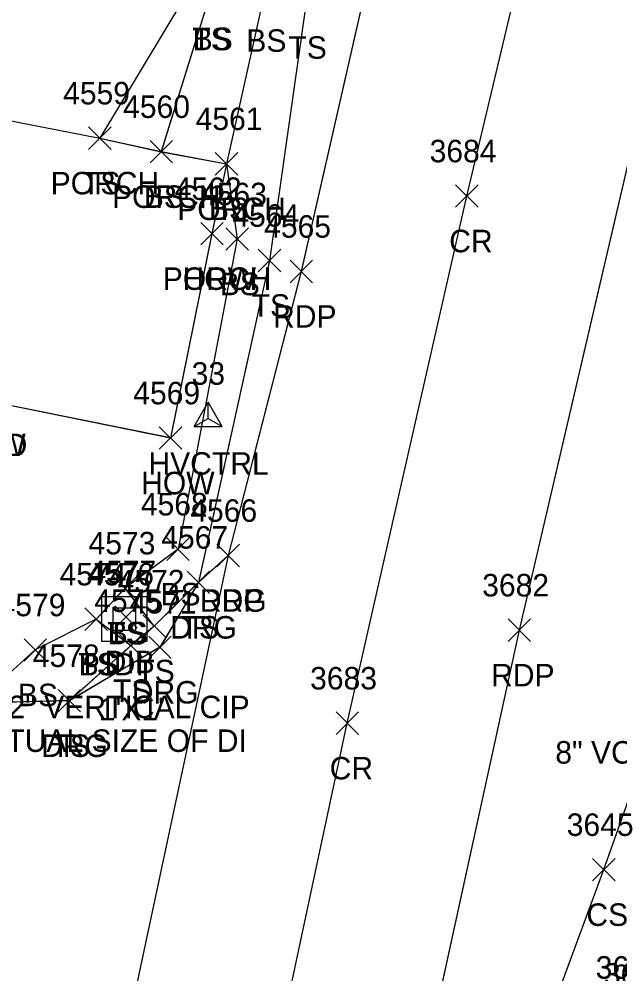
# Model space of a CAD drawing. Extents: x 1554668 to 1563881, y 831386 to 834374.
# Drawn here: x 1562427.9 to 1562481.4, y 833776.4 to 833861.3 of the extents above; entities that cross this region are included whole.
import ezdxf

# ---------------------------------------------------------------- set-up
doc = ezdxf.new("R2010")
doc.units = 0
for name, color, linetype in [('C_A', 7, 'Continuous'), ('C_I', 7, 'Continuous'), ('CPSM', 7, 'Continuous'), ('D_A', 7, 'Continuous'), ('D_C', 7, 'Continuous'), ('D_I', 7, 'Continuous'), ('D_TIC', 7, 'Continuous'), ('DS', 7, 'Continuous'), ('L_A', 7, 'Continuous'), ('L_I', 7, 'Continuous'), ('L_TIC', 7, 'Continuous'), ('LBC', 7, 'Continuous'), ('LBF', 7, 'Continuous'), ('LELB', 7, 'Continuous'), ('P_A', 7, 'Continuous'), ('P_I', 7, 'Continuous'), ('P_TIC', 7, 'Continuous'), ('PET', 7, 'Continuous'), ('PRC', 7, 'Continuous'), ('R_A', 7, 'Continuous'), ('R_I', 7, 'Continuous'), ('R_TIC', 7, 'Continuous'), ('RDG', 7, 'Continuous')]:
    doc.layers.add(name, color=color, linetype=linetype)

msp = doc.modelspace()

# ---------------------------------------------------------------- linework, layer by layer
at = {"layer": 'CPSM'}
for p, q in [((1562443.481, 833825.025), (1562444.731, 833827.19)), ((1562445.981, 833825.025), (1562444.731, 833827.19)), ((1562444.732, 833825.746), (1562444.731, 833827.19)), ((1562443.481, 833825.025), (1562444.732, 833825.746)), ((1562444.732, 833825.746), (1562444.732, 833825.746)), ((1562444.732, 833825.746), (1562445.981, 833825.025)), ((1562443.481, 833825.025), (1562445.981, 833825.025))]:
    msp.add_line(p, q, dxfattribs=at)
at = {"layer": 'D_TIC'}
for points in [[(1562436.431, 833807.096), (1562438.431, 833809.096)], [(1562438.431, 833807.096), (1562436.431, 833809.096)]]:
    msp.add_lwpolyline(points, dxfattribs=at)
at = {"layer": 'DS'}
for p, q in [((1562435.276, 833809.905), (1562439.276, 833809.905)), ((1562435.276, 833805.905), (1562435.276, 833809.905)), ((1562439.276, 833809.905), (1562439.276, 833805.905)), ((1562436.276, 833806.905), (1562436.276, 833808.905)), ((1562436.276, 833808.905), (1562438.276, 833808.905)), ((1562438.276, 833808.905), (1562438.276, 833806.905)), ((1562437.281, 833807.906), (1562437.281, 833807.906)), ((1562437.281, 833807.906), (1562437.281, 833807.906)), ((1562438.276, 833806.905), (1562436.276, 833806.905)), ((1562439.276, 833805.905), (1562435.276, 833805.905))]:
    msp.add_line(p, q, dxfattribs=at)
at = {"layer": 'L_TIC'}
for points in [[(1562434.102, 833849.67), (1562436.102, 833851.67)], [(1562436.102, 833849.67), (1562434.102, 833851.67)], [(1562434.102, 833849.67), (1562436.102, 833851.67)], [(1562436.102, 833849.67), (1562434.102, 833851.67)], [(1562439.566, 833848.466), (1562441.566, 833850.466)], [(1562441.566, 833848.466), (1562439.566, 833850.466)], [(1562439.566, 833848.466), (1562441.566, 833850.466)], [(1562441.566, 833848.466), (1562439.566, 833850.466)], [(1562445.365, 833847.39), (1562447.365, 833849.39)], [(1562447.365, 833847.39), (1562445.365, 833849.39)], [(1562445.365, 833847.39), (1562447.365, 833849.39)], [(1562447.365, 833847.39), (1562445.365, 833849.39)], [(1562444.076, 833841.176), (1562446.076, 833843.176)], [(1562446.076, 833841.176), (1562444.076, 833843.176)], [(1562444.076, 833841.176), (1562446.076, 833843.176)], [(1562446.076, 833841.176), (1562444.076, 833843.176)], [(1562446.325, 833840.702), (1562448.325, 833842.702)], [(1562448.325, 833840.702), (1562446.325, 833842.702)], [(1562449.199, 833838.787), (1562451.199, 833840.787)], [(1562451.199, 833838.787), (1562449.199, 833840.787)], [(1562440.389, 833823.003), (1562442.389, 833825.003)], [(1562442.389, 833823.003), (1562440.389, 833825.003)], [(1562441.057, 833813.122), (1562443.057, 833815.122)], [(1562443.057, 833813.122), (1562441.057, 833815.122)], [(1562442.872, 833810.172), (1562444.872, 833812.172)], [(1562444.872, 833810.172), (1562442.872, 833812.172)], [(1562436.353, 833809.658), (1562438.353, 833811.658)], [(1562438.353, 833809.658), (1562436.353, 833811.658)], [(1562436.353, 833809.658), (1562438.353, 833811.658)], [(1562438.353, 833809.658), (1562436.353, 833811.658)], [(1562433.776, 833806.899), (1562435.776, 833808.899)], [(1562435.776, 833806.899), (1562433.776, 833808.899)], [(1562433.776, 833806.899), (1562435.776, 833808.899)], [(1562435.776, 833806.899), (1562433.776, 833808.899)], [(1562438.94, 833806.285), (1562440.94, 833808.285)], [(1562440.94, 833806.285), (1562438.94, 833808.285)], [(1562438.94, 833806.285), (1562440.94, 833808.285)], [(1562440.94, 833806.285), (1562438.94, 833808.285)], [(1562428.359, 833804.16), (1562430.359, 833806.16)], [(1562430.359, 833804.16), (1562428.359, 833806.16)], [(1562436.862, 833804.544), (1562438.862, 833806.544)], [(1562438.862, 833804.544), (1562436.862, 833806.544)], [(1562436.862, 833804.544), (1562438.862, 833806.544)], [(1562438.862, 833804.544), (1562436.862, 833806.544)], [(1562431.393, 833799.647), (1562433.393, 833801.647)], [(1562433.393, 833799.647), (1562431.393, 833801.647)], [(1562478.951, 833784.626), (1562480.951, 833786.626)], [(1562480.951, 833784.626), (1562478.951, 833786.626)]]:
    msp.add_lwpolyline(points, dxfattribs=at)
at = {"layer": 'LBC'}
for points in [[(1562445.075, 833842.183), (1562441.39, 833824.008), (1562424.584, 833827.399), (1562417.372, 833829.227), (1562419.41, 833839.49), (1562412.483, 833840.561)], [(1562445.075, 833842.183), (1562441.39, 833824.008), (1562424.584, 833827.399), (1562417.372, 833829.227), (1562419.41, 833839.49), (1562412.483, 833840.561)], [(1562445.075, 833842.183), (1562441.39, 833824.008), (1562424.584, 833827.399), (1562417.372, 833829.227), (1562419.41, 833839.49), (1562412.483, 833840.561)], [(1562445.076, 833842.176), (1562441.389, 833824.003), (1562424.584, 833827.394), (1562417.373, 833829.217), (1562419.412, 833839.485), (1562412.484, 833840.549)]]:
    msp.add_lwpolyline(points, dxfattribs=at)
at = {"layer": 'LBF'}
for points in [[(1562422.129, 833851.258), (1562422.749, 833853.075), (1562435.102, 833850.67), (1562440.566, 833849.466), (1562446.365, 833848.39), (1562445.076, 833842.176)], [(1562422.132, 833851.267), (1562422.749, 833853.081), (1562435.102, 833850.678), (1562440.566, 833849.476), (1562446.364, 833848.399), (1562445.075, 833842.183)], [(1562422.132, 833851.267), (1562422.749, 833853.081), (1562435.102, 833850.678), (1562440.566, 833849.476), (1562446.364, 833848.399), (1562445.075, 833842.183)], [(1562422.132, 833851.267), (1562422.749, 833853.081), (1562435.102, 833850.678), (1562440.566, 833849.476), (1562446.364, 833848.399), (1562445.075, 833842.183)]]:
    msp.add_lwpolyline(points, dxfattribs=at)
at = {"layer": 'LELB'}
for points in [[(1562476.834, 833955.648), (1562468.679, 833926.894), (1562468.902, 833924.609), (1562461.224, 833893.664), (1562455.205, 833877.118), (1562454.79, 833874.975), (1562449.701, 833863.357), (1562446.364, 833848.399), (1562447.324, 833841.707), (1562442.057, 833814.133), (1562437.353, 833810.667)], [(1562476.834, 833955.648), (1562468.679, 833926.894), (1562468.902, 833924.609), (1562461.224, 833893.664), (1562455.205, 833877.118), (1562454.79, 833874.975), (1562449.701, 833863.357), (1562446.364, 833848.399), (1562447.324, 833841.707), (1562442.057, 833814.133), (1562437.353, 833810.667)], [(1562476.834, 833955.648), (1562468.679, 833926.894), (1562468.902, 833924.609), (1562461.224, 833893.664), (1562455.205, 833877.118), (1562454.79, 833874.975), (1562449.701, 833863.357), (1562446.364, 833848.399), (1562447.324, 833841.707), (1562442.057, 833814.133), (1562437.353, 833810.667)], [(1562476.835, 833955.638), (1562468.678, 833926.886), (1562468.901, 833924.601), (1562461.216, 833893.654), (1562455.204, 833877.112), (1562454.789, 833874.968), (1562449.695, 833863.347), (1562446.365, 833848.39), (1562447.325, 833841.702), (1562442.057, 833814.122), (1562437.353, 833810.658)], [(1562466.529, 833927.967), (1562468.679, 833926.894), (1562471.345, 833925.231), (1562463.359, 833893.198), (1562459.518, 833878.813), (1562457.062, 833872.471), (1562453.473, 833862.736), (1562450.2, 833839.796), (1562443.872, 833811.177), (1562439.94, 833807.289), (1562437.862, 833805.547), (1562432.393, 833800.653)], [(1562466.529, 833927.967), (1562468.679, 833926.894), (1562471.345, 833925.231), (1562463.359, 833893.198), (1562459.518, 833878.813), (1562457.062, 833872.471), (1562453.473, 833862.736), (1562450.2, 833839.796), (1562443.872, 833811.177), (1562439.94, 833807.289), (1562437.862, 833805.547), (1562432.393, 833800.653)], [(1562466.529, 833927.967), (1562468.679, 833926.894), (1562471.345, 833925.231), (1562463.359, 833893.198), (1562459.518, 833878.813), (1562457.062, 833872.471), (1562453.473, 833862.736), (1562450.2, 833839.796), (1562443.872, 833811.177), (1562439.94, 833807.289), (1562437.862, 833805.547), (1562432.393, 833800.653)], [(1562466.528, 833927.959), (1562468.678, 833926.886), (1562471.341, 833925.223), (1562463.35, 833893.188), (1562459.51, 833878.803), (1562457.062, 833872.466), (1562453.47, 833862.729), (1562450.199, 833839.787), (1562443.872, 833811.172), (1562439.94, 833807.285), (1562437.862, 833805.544), (1562432.393, 833800.647)], [(1562468.902, 833924.609), (1562467.61, 833924.93), (1562459.794, 833894.194), (1562453.32, 833877.396), (1562452.695, 833874.807), (1562444.925, 833863.497), (1562440.566, 833849.476)], [(1562468.902, 833924.609), (1562467.61, 833924.93), (1562459.794, 833894.194), (1562453.32, 833877.396), (1562452.695, 833874.807), (1562444.925, 833863.497), (1562440.566, 833849.476)], [(1562468.902, 833924.609), (1562467.61, 833924.93), (1562459.794, 833894.194), (1562453.32, 833877.396), (1562452.695, 833874.807), (1562444.925, 833863.497), (1562440.566, 833849.476)], [(1562468.901, 833924.601), (1562467.612, 833924.922), (1562459.786, 833894.185), (1562453.32, 833877.39), (1562452.694, 833874.801), (1562444.919, 833863.488), (1562440.566, 833849.466)], [(1562470.712, 833752.478), (1562474.337, 833770.456), (1562479.951, 833785.626), (1562485.543, 833801.396), (1562491.302, 833804.223), (1562493.844, 833813.304), (1562489.93, 833819.122), (1562484.169, 833819.958), (1562491.716, 833857.447), (1562503.171, 833893.196)], [(1562470.713, 833752.487), (1562474.337, 833770.46), (1562479.948, 833785.634), (1562485.546, 833801.399), (1562491.303, 833804.228), (1562493.845, 833813.309), (1562489.932, 833819.127), (1562484.169, 833819.963), (1562491.72, 833857.455), (1562503.176, 833893.205)], [(1562470.713, 833752.487), (1562474.337, 833770.46), (1562479.948, 833785.634), (1562485.546, 833801.399), (1562491.303, 833804.228), (1562493.845, 833813.309), (1562489.932, 833819.127), (1562484.169, 833819.963), (1562491.72, 833857.455), (1562503.176, 833893.205)], [(1562470.713, 833752.487), (1562474.337, 833770.46), (1562479.948, 833785.634), (1562485.546, 833801.399), (1562491.303, 833804.228), (1562493.845, 833813.309), (1562489.932, 833819.127), (1562484.169, 833819.963), (1562491.72, 833857.455), (1562503.176, 833893.205)], [(1562447.141, 833880.224), (1562444.644, 833873.522), (1562444.558, 833866.42), (1562435.102, 833850.678)], [(1562447.141, 833880.224), (1562444.644, 833873.522), (1562444.558, 833866.42), (1562435.102, 833850.678)], [(1562447.141, 833880.224), (1562444.644, 833873.522), (1562444.558, 833866.42), (1562435.102, 833850.678)], [(1562447.145, 833880.221), (1562444.645, 833873.518), (1562444.558, 833866.41), (1562435.102, 833850.67)], [(1562439.94, 833807.289), (1562437.353, 833810.667), (1562434.776, 833807.902), (1562437.862, 833805.547)], [(1562439.94, 833807.289), (1562437.353, 833810.667), (1562434.776, 833807.902), (1562437.862, 833805.547)], [(1562439.94, 833807.289), (1562437.353, 833810.667), (1562434.776, 833807.902), (1562437.862, 833805.547)], [(1562439.94, 833807.285), (1562437.353, 833810.658), (1562434.776, 833807.899), (1562437.862, 833805.544)], [(1562434.776, 833807.902), (1562429.358, 833805.169), (1562424.083, 833800.435)], [(1562434.776, 833807.902), (1562429.358, 833805.169), (1562424.083, 833800.435)], [(1562434.776, 833807.902), (1562429.358, 833805.169), (1562424.083, 833800.435)], [(1562434.776, 833807.899), (1562429.359, 833805.16), (1562424.084, 833800.427)]]:
    msp.add_lwpolyline(points, dxfattribs=at)
at = {"layer": 'P_TIC'}
for points in [[(1562466.753, 833844.523), (1562468.753, 833846.523)], [(1562468.753, 833844.523), (1562466.753, 833846.523)], [(1562452.027, 833837.818), (1562454.027, 833839.818)], [(1562454.027, 833837.818), (1562452.027, 833839.818)], [(1562445.513, 833812.556), (1562447.513, 833814.556)], [(1562447.513, 833812.556), (1562445.513, 833814.556)], [(1562471.429, 833805.92), (1562473.429, 833807.92)], [(1562473.429, 833805.92), (1562471.429, 833807.92)], [(1562456.117, 833797.648), (1562458.117, 833799.648)], [(1562458.117, 833797.648), (1562456.117, 833799.648)]]:
    msp.add_lwpolyline(points, dxfattribs=at)
at = {"layer": 'PET'}
for points in [[(1562390.311, 833375.989), (1562393.977, 833397.67), (1562399.624, 833430.723), (1562404.076, 833456.64), (1562408.479, 833482.044), (1562418.419, 833535.55), (1562424.853, 833574.142), (1562431.347, 833605.093), (1562438.205, 833641.603), (1562449.823, 833698.96), (1562455.982, 833728.945), (1562464.252, 833769.476), (1562472.427, 833806.927), (1562484.773, 833859.846), (1562495.065, 833901.936), (1562505.742, 833945.836), (1562515.589, 833982.411), (1562522.272, 834008.538), (1562529.881, 834035.713), (1562547.387, 834091.493), (1562561.695, 834132.946), (1562566.268, 834145.816)], [(1562390.311, 833375.989), (1562393.977, 833397.67), (1562399.624, 833430.723), (1562404.076, 833456.64), (1562408.479, 833482.044), (1562418.419, 833535.55), (1562424.853, 833574.142), (1562431.347, 833605.093), (1562438.205, 833641.603), (1562449.823, 833698.96), (1562455.982, 833728.945), (1562464.252, 833769.476), (1562472.427, 833806.927), (1562484.773, 833859.846), (1562495.065, 833901.936), (1562505.742, 833945.836), (1562515.589, 833982.411), (1562522.272, 834008.538), (1562529.881, 834035.713), (1562547.387, 834091.493), (1562561.695, 834132.946), (1562566.268, 834145.816)], [(1562390.311, 833375.989), (1562393.977, 833397.67), (1562399.624, 833430.723), (1562404.076, 833456.64), (1562408.479, 833482.044), (1562418.419, 833535.55), (1562424.853, 833574.142), (1562431.347, 833605.093), (1562438.205, 833641.603), (1562449.823, 833698.96), (1562455.982, 833728.945), (1562464.252, 833769.476), (1562472.427, 833806.927), (1562484.773, 833859.846), (1562495.065, 833901.936), (1562505.742, 833945.836), (1562515.589, 833982.411), (1562522.272, 834008.538), (1562529.881, 834035.713), (1562547.387, 834091.493), (1562561.695, 834132.946), (1562566.268, 834145.816)], [(1562390.312, 833375.983), (1562393.977, 833397.668), (1562399.627, 833430.715), (1562404.077, 833456.635), (1562408.483, 833482.042), (1562418.422, 833535.549), (1562424.854, 833574.14), (1562431.348, 833605.09), (1562438.2, 833641.597), (1562449.823, 833698.953), (1562455.981, 833728.934), (1562464.252, 833769.469), (1562472.429, 833806.92), (1562484.77, 833859.84), (1562495.065, 833901.93), (1562505.741, 833945.826), (1562515.584, 833982.407), (1562522.267, 834008.535), (1562529.877, 834035.701), (1562547.383, 834091.48), (1562561.691, 834132.936), (1562566.264, 834145.807)], [(1562435.459, 834067.179), (1562467.01, 834059.144), (1562485.949, 834051.808), (1562489.315, 834049.467), (1562496.216, 834039.663), (1562499.641, 834027.091), (1562496.942, 834013.671), (1562484.997, 833969.829), (1562474.119, 833928.894), (1562465.329, 833892.835), (1562453.027, 833838.818), (1562446.513, 833813.556), (1562435.697, 833762.843)], [(1562435.465, 834067.183), (1562467.015, 834059.149), (1562485.955, 834051.812), (1562489.324, 834049.47), (1562496.226, 834039.666), (1562499.647, 834027.095), (1562496.946, 834013.679), (1562485.004, 833969.835), (1562474.119, 833928.902), (1562465.328, 833892.841), (1562453.028, 833838.829), (1562446.514, 833813.563), (1562435.7, 833762.854)], [(1562435.465, 834067.183), (1562467.015, 834059.149), (1562485.955, 834051.812), (1562489.324, 834049.47), (1562496.226, 834039.666), (1562499.647, 834027.095), (1562496.946, 834013.679), (1562485.004, 833969.835), (1562474.119, 833928.902), (1562465.328, 833892.841), (1562453.028, 833838.829), (1562446.514, 833813.563), (1562435.7, 833762.854)], [(1562435.465, 834067.183), (1562467.015, 834059.149), (1562485.955, 834051.812), (1562489.324, 834049.47), (1562496.226, 834039.666), (1562499.647, 834027.095), (1562496.946, 834013.679), (1562485.004, 833969.835), (1562474.119, 833928.902), (1562465.328, 833892.841), (1562453.028, 833838.829), (1562446.514, 833813.563), (1562435.7, 833762.854)]]:
    msp.add_lwpolyline(points, dxfattribs=at)
at = {"layer": 'PRC'}
for points in [[(1562374.328, 833358.788), (1562379.819, 833391.645), (1562386.805, 833432.043), (1562394.132, 833473.552), (1562401.52, 833515.146), (1562408.626, 833554.57), (1562418.317, 833607.158), (1562425.122, 833644.153), (1562437.129, 833703.517), (1562446.816, 833750.468), (1562457.117, 833798.654), (1562467.75, 833845.524), (1562476.843, 833883.646), (1562492.325, 833945.243), (1562502.519, 833985.558), (1562516.732, 834038.229), (1562535.447, 834096.625), (1562549.682, 834139.255), (1562553.417, 834150.261)], [(1562374.328, 833358.788), (1562379.819, 833391.645), (1562386.805, 833432.043), (1562394.132, 833473.552), (1562401.52, 833515.146), (1562408.626, 833554.57), (1562418.317, 833607.158), (1562425.122, 833644.153), (1562437.129, 833703.517), (1562446.816, 833750.468), (1562457.117, 833798.654), (1562467.75, 833845.524), (1562476.843, 833883.646), (1562492.325, 833945.243), (1562502.519, 833985.558), (1562516.732, 834038.229), (1562535.447, 834096.625), (1562549.682, 834139.255), (1562553.417, 834150.261)], [(1562374.328, 833358.788), (1562379.819, 833391.645), (1562386.805, 833432.043), (1562394.132, 833473.552), (1562401.52, 833515.146), (1562408.626, 833554.57), (1562418.317, 833607.158), (1562425.122, 833644.153), (1562437.129, 833703.517), (1562446.816, 833750.468), (1562457.117, 833798.654), (1562467.75, 833845.524), (1562476.843, 833883.646), (1562492.325, 833945.243), (1562502.519, 833985.558), (1562516.732, 834038.229), (1562535.447, 834096.625), (1562549.682, 834139.255), (1562553.417, 834150.261)], [(1562374.328, 833358.78), (1562379.82, 833391.635), (1562386.804, 833432.041), (1562394.133, 833473.548), (1562401.522, 833515.144), (1562408.625, 833554.563), (1562418.32, 833607.155), (1562425.125, 833644.147), (1562437.128, 833703.511), (1562446.815, 833750.458), (1562457.117, 833798.648), (1562467.753, 833845.523), (1562476.843, 833883.643), (1562492.321, 833945.235), (1562502.515, 833985.553), (1562516.728, 834038.221), (1562535.444, 834096.612), (1562549.678, 834139.252), (1562553.413, 834150.251)]]:
    msp.add_lwpolyline(points, dxfattribs=at)
at = {"layer": 'R_TIC'}
for points in [[(1562445.513, 833812.556), (1562447.513, 833814.556)], [(1562447.513, 833812.556), (1562445.513, 833814.556)], [(1562442.872, 833810.172), (1562444.872, 833812.172)], [(1562444.872, 833810.172), (1562442.872, 833812.172)], [(1562439.453, 833804.4), (1562441.453, 833806.4)], [(1562441.453, 833804.4), (1562439.453, 833806.4)], [(1562431.393, 833799.647), (1562433.393, 833801.647)], [(1562433.393, 833799.647), (1562431.393, 833801.647)]]:
    msp.add_lwpolyline(points, dxfattribs=at)
at = {"layer": 'RDG'}
for points in [[(1562446.514, 833813.563), (1562443.872, 833811.177), (1562440.454, 833805.407), (1562432.393, 833800.653), (1562424.083, 833800.435), (1562417.273, 833767.263), (1562421.889, 833758.153), (1562425.326, 833750.474), (1562429.669, 833734.264)], [(1562446.514, 833813.563), (1562443.872, 833811.177), (1562440.454, 833805.407), (1562432.393, 833800.653), (1562424.083, 833800.435), (1562417.273, 833767.263), (1562421.889, 833758.153), (1562425.326, 833750.474), (1562429.669, 833734.264)], [(1562446.514, 833813.563), (1562443.872, 833811.177), (1562440.454, 833805.407), (1562432.393, 833800.653), (1562424.083, 833800.435), (1562417.273, 833767.263), (1562421.889, 833758.153), (1562425.326, 833750.474), (1562429.669, 833734.264)], [(1562446.513, 833813.556), (1562443.872, 833811.172), (1562440.453, 833805.4), (1562432.393, 833800.647), (1562424.084, 833800.427), (1562417.274, 833767.254), (1562421.893, 833758.146), (1562425.324, 833750.465), (1562429.671, 833734.255)]]:
    msp.add_lwpolyline(points, dxfattribs=at)

# ---------------------------------------------------------------- texts
at = {"layer": 'C_A'}
msp.add_text('HVCTRL', height=2, dxfattribs=at).set_placement((1562439.424, 833820.746))
at = {"layer": 'C_I'}
msp.add_text('33', height=2, dxfattribs=at).set_placement((1562443.267, 833828.746))
at = {"layer": 'D_A'}
for s, p in [('DIB', (1562435.533, 833803.096)), ('DI', (1562436.336, 833802.906))]:
    msp.add_text(s, height=2, dxfattribs=at).set_placement(p)
at = {"layer": 'D_C'}
for s, p in [('12" VERTICAL CIP', (1562425.486, 833799.096)), ("1'X1'", (1562435.013, 833798.906)), ('ACTUAL SIZE OF DI', (1562423.068, 833796.096)), ('8" VCP FLOWING EAST', (1562475.625, 833795.057))]:
    msp.add_text(s, height=2, dxfattribs=at).set_placement(p)
at = {"layer": 'D_I'}
for s, p in [('4577', (1562434.171, 833811.096)), ('4576', (1562433.966, 833810.906))]:
    msp.add_text(s, height=2, dxfattribs=at).set_placement(p)
at = {"layer": 'L_A'}
for s, p in [('TS', (1562443.329, 833858.488)), ('BS', (1562443.36, 833858.488)), ('BS', (1562448.136, 833858.347)), ('TS', (1562451.88, 833857.729)), ('PORCH', (1562430.725, 833845.67)), ('TS', (1562433.512, 833845.67)), ('PORCH', (1562436.188, 833844.466)), ('BS', (1562439.007, 833844.466)), ('PORCH', (1562441.987, 833843.39)), ('BS', (1562444.806, 833843.39)), ('PORCH', (1562440.698, 833837.176)), ('HOW', (1562442.462, 833837.176)), ('BS', (1562445.766, 833836.702)), ('TS', (1562448.609, 833834.787)), ('SHED', (1562421.222, 833822.394)), ('HOW', (1562421.97, 833822.394)), ('HOW', (1562438.775, 833819.003)), ('BS', (1562440.498, 833809.122)), ('TS', (1562442.281, 833806.172)), ('TS', (1562435.762, 833805.658)), ('BS', (1562435.794, 833805.658)), ('TS', (1562433.185, 833802.899)), ('BS', (1562433.216, 833802.899)), ('TS', (1562438.349, 833802.285)), ('TS', (1562438.349, 833802.285)), ('BS', (1562427.8, 833800.16)), ('TS', (1562436.271, 833800.544)), ('TS', (1562436.271, 833800.544)), ('TS', (1562430.802, 833795.647)), ('CS', (1562478.392, 833780.626))]:
    msp.add_text(s, height=2, dxfattribs=at).set_placement(p)
at = {"layer": 'L_I'}
for s, p in [('4559', (1562431.835, 833853.67)), ('4559', (1562431.835, 833853.67)), ('4560', (1562437.172, 833852.466)), ('4560', (1562437.172, 833852.466)), ('4561', (1562443.625, 833851.39)), ('4561', (1562443.625, 833851.39)), ('4562', (1562441.769, 833845.176)), ('4562', (1562441.769, 833845.176)), ('4563', (1562444.018, 833844.702)), ('4564', (1562446.892, 833842.787)), ('4569', (1562438.074, 833827.003)), ('4568', (1562438.75, 833817.122)), ('4573', (1562434.093, 833813.658)), ('4573', (1562434.093, 833813.658)), ('4567', (1562440.565, 833814.172)), ('4574', (1562431.516, 833810.899)), ('4574', (1562431.516, 833810.899)), ('4572', (1562436.68, 833810.285)), ('4572', (1562436.68, 833810.285)), ('4575', (1562434.602, 833808.544)), ('4575', (1562434.602, 833808.544)), ('4579', (1562426.091, 833808.16)), ('4578', (1562429.133, 833803.647)), ('3645', (1562476.644, 833788.626)), ('3642', (1562479.218, 833775.932)), ('3641', (1562479.949, 833775.314))]:
    msp.add_text(s, height=2, dxfattribs=at).set_placement(p)
at = {"layer": 'P_A'}
for s, p in [('CR', (1562466.186, 833840.523)), ('RDP', (1562450.515, 833833.818)), ('RDP', (1562444.001, 833808.556)), ('RDP', (1562469.917, 833801.92)), ('CR', (1562455.55, 833793.648))]:
    msp.add_text(s, height=2, dxfattribs=at).set_placement(p)
at = {"layer": 'P_I'}
for s, p in [('3684', (1562464.446, 833848.523)), ('4565', (1562449.72, 833841.818)), ('4566', (1562443.151, 833816.556)), ('3682', (1562469.122, 833809.92)), ('3683', (1562453.81, 833801.648))]:
    msp.add_text(s, height=2, dxfattribs=at).set_placement(p)
at = {"layer": 'R_A'}
for p in [(1562444.001, 833808.556), (1562441.36, 833806.172), (1562437.942, 833800.4), (1562429.881, 833795.647)]:
    msp.add_text('DRG', height=2, dxfattribs=at).set_placement(p)
at = {"layer": 'R_I'}
for s, p in [('4566', (1562443.151, 833816.556)), ('4567', (1562440.565, 833814.172)), ('4571', (1562437.76, 833808.4)), ('4578', (1562429.133, 833803.647)), ('3642', (1562479.218, 833775.932))]:
    msp.add_text(s, height=2, dxfattribs=at).set_placement(p)

doc.saveas('drawing.dxf')
